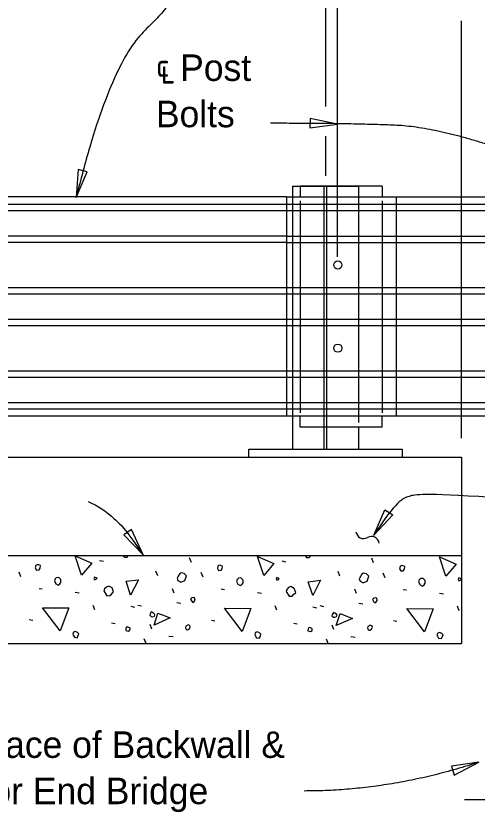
# Model space of a CAD drawing. Extents: x 21526.6 to 21598.7, y 56118.9 to 56155.9.
# Drawn here: x 21550.79 to 21554.3, y 56132.49 to 56138.57 of the extents above; entities that cross this region are included whole.
import ezdxf

# ---------------------------------------------------------------- set-up
doc = ezdxf.new("R2010")
doc.units = 0
for name, color, linetype in [('AdhocPoint_dp', 7, 'Continuous'), ('Patterning', 7, 'Continuous'), ('PlotBorder_dp', 7, 'Continuous'), ('SheetBorder_dp', 7, 'Continuous'), ('TextMisc', 7, 'Continuous')]:
    doc.layers.add(name, color=color, linetype=linetype)

msp = doc.modelspace()

# ---------------------------------------------------------------- linework, layer by layer
at = {"layer": 'AdhocPoint_dp'}
for p, q in [((21546.3955, 56135.21), (21554.1792, 56135.21)), ((21554.1792, 56135.21), (21554.1792, 56133.7933)), ((21554.1792, 56134.46), (21546.3955, 56134.46)), ((21546.3955, 56133.7933), (21554.1792, 56133.7933))]:
    msp.add_line(p, q, dxfattribs=at)
at = {"layer": 'Patterning'}
for p, q in [((21553.2368, 56136.733), (21553.2368, 56140.7989)), ((21553.1455, 56139.7166), (21553.1455, 56137.8785)), ((21553.1455, 56137.6522), (21553.1455, 56137.3509)), ((21553.5775, 56137.2724), (21552.9525, 56137.2724)), ((21552.9525, 56137.2724), (21552.9525, 56137.1891)), ((21553.5775, 56137.2724), (21553.5775, 56137.1891)), ((21552.9525, 56137.1605), (21552.9525, 56135.5487)), ((21553.5775, 56137.1605), (21553.5775, 56135.5487)), ((21546.3955, 56137.1336), (21552.8484, 56137.1336)), ((21546.3955, 56137.0854), (21552.8484, 56137.0854)), ((21546.3955, 56136.8926), (21552.8484, 56136.8926)), ((21546.3955, 56136.8444), (21552.8484, 56136.8444)), ((21546.3955, 56136.5004), (21552.8484, 56136.5004)), ((21546.3955, 56136.4522), (21552.8484, 56136.4522)), ((21546.3955, 56136.2594), (21552.8484, 56136.2594)), ((21546.3955, 56136.2112), (21552.8484, 56136.2112)), ((21546.3955, 56135.8673), (21552.8484, 56135.8673)), ((21546.3955, 56135.8191), (21552.8484, 56135.8191)), ((21546.3955, 56135.6262), (21552.8484, 56135.6262)), ((21546.3955, 56135.578), (21552.8484, 56135.578)), ((21552.9525, 56135.4391), (21552.9525, 56135.5224)), ((21553.5775, 56135.4391), (21553.5775, 56135.5224)), ((21553.5775, 56135.4391), (21552.9525, 56135.4391)), ((21551.4284, 56134.4258), (21551.4567, 56134.4187)), ((21552.1266, 56134.4099), (21552.1125, 56134.4452)), ((21552.8131, 56134.4222), (21552.8413, 56134.4152)), ((21553.5113, 56134.4063), (21553.4972, 56134.4417)), ((21550.8297, 56134.3009), (21550.8156, 56134.3362)), ((21551.8703, 56134.3091), (21551.8562, 56134.3444)), ((21552.2144, 56134.2973), (21552.2003, 56134.3327)), ((21553.255, 56134.3056), (21553.2409, 56134.3409)), ((21553.5991, 56134.2938), (21553.5849, 56134.3292)), ((21550.9676, 56134.2125), (21550.9924, 56134.209)), ((21551.2434, 56134.1842), (21551.2734, 56134.1789)), ((21551.9958, 56134.1765), (21551.9835, 56134.2101)), ((21552.3523, 56134.209), (21552.377, 56134.2054)), ((21552.6281, 56134.1807), (21552.6581, 56134.1754)), ((21553.3805, 56134.173), (21553.3681, 56134.2066)), ((21553.737, 56134.2054), (21553.7617, 56134.2019)), ((21554.0127, 56134.1771), (21554.0428, 56134.1718)), ((21551.3919, 56134.0499), (21551.3795, 56134.0834)), ((21551.6659, 56134.0764), (21551.6942, 56134.0693)), ((21551.7183, 56134.0864), (21551.7466, 56134.0793)), ((21552.0147, 56134.1047), (21552.0447, 56134.0994)), ((21552.7766, 56134.0463), (21552.7642, 56134.0799)), ((21553.0506, 56134.0728), (21553.0788, 56134.0658)), ((21553.103, 56134.0828), (21553.1313, 56134.0757)), ((21553.3993, 56134.1011), (21553.4294, 56134.0958)), ((21554.1612, 56134.0428), (21554.1489, 56134.0764)), ((21550.8934, 56133.9756), (21550.9199, 56133.9703)), ((21551.5192, 56133.9509), (21551.5457, 56133.9456)), ((21551.8244, 56133.9038), (21551.812, 56133.9373)), ((21552.278, 56133.9721), (21552.3046, 56133.9668)), ((21552.9038, 56133.9473), (21552.9304, 56133.942)), ((21553.209, 56133.9002), (21553.1967, 56133.9338)), ((21553.6627, 56133.9685), (21553.6892, 56133.9632)), ((21551.7819, 56133.7942), (21551.7678, 56133.8295)), ((21551.9545, 56133.8501), (21551.9864, 56133.8466)), ((21553.1655, 56133.7933), (21553.1525, 56133.826)), ((21553.3392, 56133.8466), (21553.371, 56133.843))]:
    msp.add_line(p, q, dxfattribs=at)
for points in [[(21551.2911, 56134.3133), (21551.2434, 56134.46), (21551.3689, 56134.4052), (21551.2911, 56134.3133)], [(21551.6117, 56134.46), (21551.6158, 56134.4505), (21551.6122, 56134.454)], [(21551.6158, 56134.4505), (21551.637, 56134.4505), (21551.6464, 56134.46)], [(21552.6758, 56134.3097), (21552.6281, 56134.4564), (21552.7536, 56134.4016), (21552.6758, 56134.3097)], [(21552.9955, 56134.46), (21552.9951, 56134.4594), (21553.0004, 56134.447), (21552.9969, 56134.4505)], [(21553.0004, 56134.447), (21553.0217, 56134.447), (21553.0323, 56134.4576), (21553.0316, 56134.46)], [(21554.0605, 56134.3062), (21554.0127, 56134.4529), (21554.1383, 56134.3981), (21554.0605, 56134.3062)], [(21550.9393, 56134.3681), (21550.9482, 56134.3521), (21550.9676, 56134.3539), (21550.9765, 56134.3663), (21550.9782, 56134.3857), (21550.9658, 56134.391), (21550.957, 56134.3928), (21550.9464, 56134.3893), (21550.9429, 56134.3857), (21550.9393, 56134.3681)], [(21552.324, 56134.3645), (21552.3328, 56134.3486), (21552.3523, 56134.3504), (21552.3611, 56134.3627), (21552.3629, 56134.3822), (21552.3505, 56134.3875), (21552.3417, 56134.3893), (21552.3311, 56134.3857), (21552.3275, 56134.3822), (21552.324, 56134.3645)], [(21553.7087, 56134.361), (21553.7175, 56134.3451), (21553.737, 56134.3468), (21553.7458, 56134.3592), (21553.7476, 56134.3787), (21553.7352, 56134.384), (21553.7264, 56134.3857), (21553.7158, 56134.3822), (21553.7122, 56134.3787), (21553.7087, 56134.361)], [(21551.0843, 56134.2691), (21551.0949, 56134.2478), (21551.1126, 56134.2372), (21551.1267, 56134.2478), (21551.1338, 56134.2585), (21551.1338, 56134.2797), (21551.1179, 56134.2956), (21551.0984, 56134.2938), (21551.0896, 56134.285), (21551.0843, 56134.2691)], [(21551.3901, 56134.2779), (21551.4096, 56134.2867), (21551.4025, 56134.2938), (21551.3901, 56134.2991), (21551.3848, 56134.2867), (21551.3901, 56134.2779)], [(21552.0241, 56134.272), (21552.0471, 56134.2596), (21552.0771, 56134.272), (21552.0895, 56134.3091), (21552.0718, 56134.3268), (21552.0489, 56134.3321), (21552.0383, 56134.325), (21552.0259, 56134.3056), (21552.017, 56134.2896), (21552.0241, 56134.272)], [(21552.7748, 56134.2744), (21552.7942, 56134.2832), (21552.7872, 56134.2903), (21552.7748, 56134.2956), (21552.7695, 56134.2832), (21552.7748, 56134.2744)], [(21553.4088, 56134.2684), (21553.4318, 56134.2561), (21553.4618, 56134.2684), (21553.4742, 56134.3056), (21553.4565, 56134.3232), (21553.4335, 56134.3285), (21553.4229, 56134.3215), (21553.4106, 56134.302), (21553.4017, 56134.2861), (21553.4088, 56134.2684)], [(21551.6635, 56134.1624), (21551.6299, 56134.2667), (21551.7236, 56134.279), (21551.6635, 56134.1624)], [(21552.469, 56134.2655), (21552.4796, 56134.2443), (21552.4973, 56134.2337), (21552.5114, 56134.2443), (21552.5185, 56134.2549), (21552.5185, 56134.2761), (21552.5026, 56134.292), (21552.4831, 56134.2903), (21552.4743, 56134.2814), (21552.469, 56134.2655)], [(21553.0482, 56134.1588), (21553.0146, 56134.2631), (21553.1083, 56134.2755), (21553.0482, 56134.1588)], [(21553.8536, 56134.262), (21553.8643, 56134.2408), (21553.8819, 56134.2302), (21553.8961, 56134.2408), (21553.9031, 56134.2514), (21553.9031, 56134.2726), (21553.8872, 56134.2885), (21553.8678, 56134.2867), (21553.8589, 56134.2779), (21553.8536, 56134.262)], [(21554.1595, 56134.2708), (21554.1789, 56134.2797), (21554.1718, 56134.2867), (21554.1595, 56134.292), (21554.1542, 56134.2797), (21554.1595, 56134.2708)], [(21551.4608, 56134.193), (21551.4838, 56134.1559), (21551.5068, 56134.1577), (21551.5156, 56134.1665), (21551.5351, 56134.186), (21551.5227, 56134.216), (21551.4979, 56134.2302), (21551.4803, 56134.2231), (21551.4661, 56134.209), (21551.4608, 56134.193)], [(21552.8455, 56134.1895), (21552.8685, 56134.1524), (21552.8915, 56134.1542), (21552.9003, 56134.163), (21552.9197, 56134.1824), (21552.9074, 56134.2125), (21552.8826, 56134.2266), (21552.8649, 56134.2196), (21552.8508, 56134.2054), (21552.8455, 56134.1895)], [(21552.126, 56134.117), (21552.1366, 56134.1064), (21552.1472, 56134.1135), (21552.1543, 56134.1241), (21552.1508, 56134.1418), (21552.1419, 56134.1435), (21552.1296, 56134.1418), (21552.1189, 56134.1312), (21552.126, 56134.117)], [(21553.5107, 56134.1135), (21553.5213, 56134.1029), (21553.5319, 56134.11), (21553.539, 56134.1206), (21553.5354, 56134.1382), (21553.5266, 56134.14), (21553.5142, 56134.1382), (21553.5036, 56134.1276), (21553.5107, 56134.1135)], [(21551.1285, 56133.889), (21550.9941, 56134.0658), (21551.1939, 56134.064), (21551.1285, 56133.889)], [(21552.5132, 56133.8855), (21552.3788, 56134.0622), (21552.5786, 56134.0605), (21552.5132, 56133.8855)], [(21553.8978, 56133.8819), (21553.7635, 56134.0587), (21553.9632, 56134.0569), (21553.8978, 56133.8819)], [(21551.8208, 56133.998), (21551.8332, 56133.9962), (21551.8456, 56134.0015), (21551.8491, 56134.0121), (21551.8438, 56134.0209), (21551.8332, 56134.028), (21551.8208, 56134.0333), (21551.8138, 56134.0192), (21551.8102, 56134.0086), (21551.8208, 56133.998)], [(21551.8432, 56133.9332), (21551.8715, 56134.0251), (21551.9652, 56133.988), (21551.8432, 56133.9332)], [(21553.2055, 56133.9944), (21553.2179, 56133.9927), (21553.2302, 56133.998), (21553.2338, 56134.0086), (21553.2285, 56134.0174), (21553.2179, 56134.0245), (21553.2055, 56134.0298), (21553.1984, 56134.0156), (21553.1949, 56134.005), (21553.2055, 56133.9944)], [(21553.2279, 56133.9296), (21553.2561, 56134.0216), (21553.3498, 56133.9844), (21553.2279, 56133.9296)], [(21552.0907, 56133.8978), (21552.0977, 56133.8978), (21552.1119, 56133.9049), (21552.1172, 56133.9208), (21552.1154, 56133.9296), (21552.1013, 56133.9367), (21552.0836, 56133.9261), (21552.0801, 56133.9155), (21552.0836, 56133.9049), (21552.0907, 56133.8978)], [(21553.4753, 56133.8943), (21553.4824, 56133.8943), (21553.4966, 56133.9014), (21553.5019, 56133.9173), (21553.5001, 56133.9261), (21553.4859, 56133.9332), (21553.4683, 56133.9226), (21553.4647, 56133.912), (21553.4683, 56133.9014), (21553.4753, 56133.8943)], [(21551.2275, 56133.8572), (21551.2363, 56133.8413), (21551.2575, 56133.8377), (21551.2664, 56133.8536), (21551.2699, 56133.8678), (21551.2611, 56133.8766), (21551.2452, 56133.8855), (21551.2292, 56133.8801), (21551.2239, 56133.8642), (21551.2275, 56133.8572)], [(21551.627, 56133.8925), (21551.6464, 56133.8872), (21551.6588, 56133.8961), (21551.6606, 56133.9084), (21551.657, 56133.912), (21551.6429, 56133.919), (21551.6305, 56133.9173), (21551.6288, 56133.9049), (21551.627, 56133.8925)], [(21552.6122, 56133.8536), (21552.621, 56133.8377), (21552.6422, 56133.8342), (21552.651, 56133.8501), (21552.6546, 56133.8642), (21552.6457, 56133.8731), (21552.6298, 56133.8819), (21552.6139, 56133.8766), (21552.6086, 56133.8607), (21552.6122, 56133.8536)], [(21553.0117, 56133.889), (21553.0311, 56133.8837), (21553.0435, 56133.8925), (21553.0453, 56133.9049), (21553.0417, 56133.9084), (21553.0276, 56133.9155), (21553.0152, 56133.9137), (21553.0134, 56133.9014), (21553.0117, 56133.889)], [(21553.9968, 56133.8501), (21554.0057, 56133.8342), (21554.0269, 56133.8307), (21554.0357, 56133.8466), (21554.0393, 56133.8607), (21554.0304, 56133.8695), (21554.0145, 56133.8784), (21553.9986, 56133.8731), (21553.9933, 56133.8572), (21553.9968, 56133.8501)]]:
    msp.add_lwpolyline(points, dxfattribs=at)
at = {"layer": 'PlotBorder_dp'}
msp.add_line((21554.1792, 56135.3555), (21554.1792, 56138.5276), dxfattribs=at)
for points in [[(21553.2368, 56137.7435), (21553.03, 56137.7865), (21553.0274, 56137.7159)], [(21551.2498, 56137.1865), (21551.334, 56137.3802), (21551.2655, 56137.3971)], [(21553.5135, 56134.6171), (21553.5976, 56134.8109), (21553.6567, 56134.7723)], [(21551.7585, 56134.4667), (21551.672, 56134.6594), (21551.6134, 56134.6201)], [(21554.3117, 56132.8915), (21554.1029, 56132.8596), (21554.1251, 56132.7926)]]:
    msp.add_lwpolyline(points, close=True, dxfattribs=at)
msp.add_lwpolyline([(21555.4018, 56132.6055), (21554.8932, 56132.6055), (21554.8932, 56132.4893), (21554.7938, 56132.7143), (21554.7938, 56132.6055), (21554.2018, 56132.6055)], dxfattribs=at)
for centre, start, end in [((21553.436, 56134.6515), 187.95358, 299.6808), ((21553.495, 56134.5479), 7.95358, 119.6808)]:
    msp.add_arc(centre, 0.0596, start, end, dxfattribs=at)
for points, degree in [([(21551.666, 56139.1156), (21551.9063, 56139.1156), (21552.0592, 56139.1156), (21552.0592, 56138.7221), (21551.5022, 56138.2085), (21551.2498, 56137.1865)], 2), ([(21552.7287, 56137.7519), (21553.3051, 56137.7529), (21554.0547, 56137.7205), (21554.7081, 56137.4746)], 2), ([(21554.4035, 56134.9046), (21553.8821, 56134.9384), (21553.7786, 56134.9162), (21553.6846, 56134.8796), (21553.5135, 56134.6171)], 3), ([(21551.3409, 56134.8727), (21551.4131, 56134.8471), (21551.5545, 56134.7387), (21551.6378, 56134.647), (21551.7585, 56134.4666)], 3), ([(21554.3117, 56132.8915), (21553.648, 56132.6719), (21552.9843, 56132.6719)], 2)]:
    msp.add_open_spline(points, degree=degree, dxfattribs=at)
at = {"layer": 'SheetBorder_dp'}
for p, q in [((21553.1351, 56135.2724), (21553.1351, 56137.2724)), ((21553.1559, 56135.2724), (21553.1559, 56137.2724)), ((21553.3955, 56137.2724), (21553.3955, 56135.4745)), ((21552.8484, 56137.1891), (21552.8484, 56135.5224)), ((21564.1633, 56137.1891), (21552.8484, 56137.1891)), ((21552.8955, 56137.1891), (21552.8955, 56135.5224)), ((21553.6817, 56137.1891), (21553.6817, 56135.5224)), ((21552.8484, 56137.1336), (21564.1633, 56137.1336)), ((21552.8484, 56137.0853), (21564.1633, 56137.0853)), ((21552.8484, 56136.8925), (21564.1633, 56136.8925)), ((21552.8484, 56136.8443), (21564.1633, 56136.8443)), ((21552.8484, 56136.5003), (21564.1633, 56136.5003)), ((21552.8484, 56136.4521), (21564.1633, 56136.4521)), ((21552.8484, 56136.2593), (21564.1633, 56136.2593)), ((21552.8484, 56136.2112), (21564.1633, 56136.2112)), ((21552.8484, 56135.8672), (21564.1633, 56135.8672)), ((21552.8484, 56135.819), (21564.1633, 56135.819)), ((21552.8484, 56135.6262), (21564.1633, 56135.6262)), ((21552.8484, 56135.5779), (21564.1633, 56135.5779)), ((21564.1633, 56135.5224), (21552.8484, 56135.5224))]:
    msp.add_line(p, q, dxfattribs=at)
at = {"layer": 'TextMisc'}
for p, q in [((21552.8955, 56137.2724), (21553.3955, 56137.2724)), ((21552.8955, 56137.2724), (21552.8955, 56137.1891)), ((21552.8484, 56137.1892), (21546.3955, 56137.1892)), ((21552.8484, 56135.5225), (21546.3955, 56135.5225)), ((21552.8955, 56135.5224), (21552.8955, 56135.2724)), ((21553.3955, 56135.4391), (21553.3955, 56135.2724)), ((21552.5621, 56135.2724), (21553.7288, 56135.2724)), ((21552.5621, 56135.2099), (21552.5621, 56135.2724)), ((21552.8955, 56135.2724), (21553.3955, 56135.2724)), ((21553.7288, 56135.2724), (21553.7288, 56135.2099)), ((21552.5621, 56135.2099), (21553.7288, 56135.2099))]:
    msp.add_line(p, q, dxfattribs=at)
for centre in [(21553.2392, 56136.6723), (21553.2392, 56136.0392)]:
    msp.add_circle(centre, 0.0312, dxfattribs=at)

# ---------------------------------------------------------------- texts
at = {"layer": 'PlotBorder_dp'}
for s, p in [('℄ Post ', (21551.8565, 56138.0718)), ('Bolts', (21551.8565, 56137.7198)), ('Front Face of Backwall &', (21549.8416, 56132.9237)), ('Begin or End Bridge', (21549.8416, 56132.5717))]:
    msp.add_text(s, height=0.2016, dxfattribs=at).set_placement(p)

doc.saveas('drawing.dxf')
